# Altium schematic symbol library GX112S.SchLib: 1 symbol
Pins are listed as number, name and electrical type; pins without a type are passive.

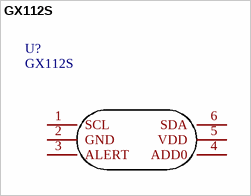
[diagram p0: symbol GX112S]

## GX112S
designator U?
footprint SOT-563-6_L1.6-W1.2-P0.5-LS1.6-BL
pins: 1 SCL, 2 GND, 3 ALERT, 4 ADD0, 5 VDD, 6 SDA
